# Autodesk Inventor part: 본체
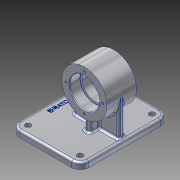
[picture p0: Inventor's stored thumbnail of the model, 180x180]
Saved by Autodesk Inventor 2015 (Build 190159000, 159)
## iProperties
Created: 2019-09
Part Number: 본체
Material: 알루미늄 6061
Document SubType Name: Modeling
Designer: Lineart
Density: 2.7 g/cm^3
Appearance: 알루미늄 - 평지
Mass: 554.62 g
Surface Area: 495.884 cm^2
Volume: 205.415 cm^3
Author: Lineart
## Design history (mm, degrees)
sketch "스케치1"
  geometry: L1 (-21, 0)-(21, 0); L2 (-21, 32)-(21, 32); L3 (-21, 21)-(-6, 21) reference; L4 (-21, 32)-(-21, 21) reference; L5 (21, 32)-(21, 21) reference; L6 (21, 21)-(6, 21) reference; L7 (6, 18)-(-6, 18) reference; L8 (-6, 18)-(-6, 21) reference; L9 (6, 21)-(6, 18); 2 further points
  constraints: 18 end point, 5 horizontal, 5 vertical, 1 coincident, 1 midpoint, 1 parallel, 1 perpendicular
  dimensions: "d0" = 42 distance of L1.start L1.end; "d1" = 32 distance between parallel lines of L1 L2; "d4" = 15 distance of L5.end L6.end
revolve "회전1" sketch "스케치1" stored, may be unused: angle "d6" = 90 deg
node "작업 평면1"
sketch "스케치2"
  geometry: L1 (0, 0)-(0, -62); L2 (63, -62)-(-63, -62); L3 (63, -62)-(63, 36); L4 (63, 36)-(-63, 36); L5 (-63, 36)-(-63, -62)
  constraints: 10 end point, 2 perpendicular, 2 vertical, 1 horizontal, 1 midpoint
  dimensions: "d8" = 62 distance of L1.end L1.start; "d9" = 126 distance of L2.start L2.end; "d10" = 98 distance of L2.start L3.end
extrude "돌출1" join sketch "스케치2" distance "d11" = 9; taper "d12" = 0 deg
sketch "스케치3"
  geometry: L1 (0, 32)-(-55.231, 32); L2 (-55.231, 32)-(-55.231, -32) reference; L3 (-55.231, -32)-(0, -32) reference; A1 r 32 centre (0, 0) between (0, 32) and (0, -32) reference; A2 r 32 centre (0, 0) between (0, 32) and (0, -32); 1 further point
  constraints: 6 end point, 4 point on circle, 2 horizontal, 2 perpendicular, 1 centre point, 1 coincident, 1 tangent, 1 vertical
extrude "돌출2" join sketch "스케치3" stored distance "d13" = 8; taper "d14" = 0 deg
sketch "스케치4"
  geometry: L1 (-17, -59)-(17, -59); L2 (-63, -59)-(63, -59) reference; L3 (-17, -22.009)-(17, -22.009) reference; L4 (-17, -22.009)-(-17, -59); L5 (17, -22.009)-(17, -59); 2 further points
  constraints: 8 end point, 2 horizontal, 2 midpoint, 2 vertical, 1 parallel
  dimensions: "d15" = 34 distance of L1.start L1.end
extrude "돌출3" join sketch "스케치4" stored distance "d16" = 8; taper "d17" = 0 deg
sketch "스케치5"
  geometry: L1 (0, 0)-(0, 26); 1 further point
  constraints: 2 end point, 1 coincident, 1 vertical
  dimensions: "d18" = 26 distance of L1.start L1.end
hole "구멍1" sketch "스케치5" at (0, 26) diameter "d19" = 3.242; stored, may be unused: countersink angle "d23" = 90 deg, drill point angle "d25" = 118 deg; dims "d20" = 8, "d21" = 4, "d22" = 2, "d24" = 10
fillet "모깎기1" dims "d29" = 12, "d30" = 3, "d46" = 0.3
fillet "모깎기2" dims "d31" = 3
chamfer "모따기1" distance "d32" = 1; stored, may be unused: second distance "d33" = 2, angle "d34" = 45 deg
sketch "스케치6"
  geometry: L1 (-51, -33)-(-5.472, -33) reference; L2 (1, -33.607)-(-1, -33.607) reference; L3 (7, -29)-(7, -7) reference; L4 (7, -7)-(14, -7) reference; L5 (20, -1)-(20, 1) reference; L6 (14, 7)-(7, 7) reference; L7 (7, 7)-(7, 29) reference; L8 (1, 35)-(-1, 35) reference; L9 (-7, 29)-(-7, 7) reference; L10 (-7, 7)-(-14, 7) reference; L11 (-20, 1)-(-20, -1) reference; L12 (-14, -7)-(-7, -7) reference; L13 (-7, -7)-(-7, -29) reference; L14 (-60, 50)-(-60, -24) reference; L15 (51, 59)-(-51, 59) reference; L16 (60, -24)-(60, 50) reference; L17 (5.472, -33)-(51, -33) reference; L18 (-63, 50)-(-63, 62); L19 (-63, 62)-(0, 62); L20 (51, 62)-(-51, 62) reference; L21 (0, 62)-(0, 52); A1 r 9 centre (-51, -24) between (-60, -24) and (-51, -33) reference; A2 r 6 centre (1, -29) between (5.472, -33) and (7, -29) reference; A3 r 6 centre (14, -1) between (14, -7) and (20, -1) reference; A4 r 6 centre (14, 1) between (20, 1) and (14, 7) reference; A5 r 6 centre (1, 29) between (7, 29) and (1, 35) reference; A6 r 6 centre (-1, 29) between (-1, 35) and (-7, 29) reference; A7 r 6 centre (-14, 1) between (-14, 7) and (-20, 1) reference; A8 r 6 centre (-14, -1) between (-20, -1) and (-14, -7) reference; A9 r 6 centre (-1, -29) between (-7, -29) and (-5.472, -33) reference; A10 r 9 centre (-51, 50) between (-51, 59) and (-60, 50) reference; A11 r 9 centre (51, 50) between (60, 50) and (51, 59) reference; A12 r 9 centre (51, -24) between (51, -33) and (60, -24) reference; A13 r 12 centre (-51, 50) between (-51, 62) and (-63, 50) reference; 2 further points
  constraints: 6 end point, 1 coincident, 1 midpoint, 1 perpendicular, 1 tangent, 1 vertical, 3 other
  dimensions: "d35" = 63 distance of L18.end L19.end; "d36" = 10 distance of L19.end L21.end
feature "엠보싱1" sketch "스케치6" dims "d37" = 0.5, "d38" = 0
sketch "스케치7"
  geometry: L1 (18.989, 51.997)-(17.659, 51.997) reference; L2 (17.659, 51.997)-(17.659, 52.377) reference; L3 (17.659, 52.377)-(18.989, 52.377) reference; L4 (18.989, 52.377)-(18.989, 54.955) reference; L5 (18.989, 54.955)-(19.315, 54.955) reference; L6 (19.45, 54.69)-(19.45, 49.018) reference; L7 (19.45, 49.018)-(18.989, 49.018) reference; L8 (18.989, 49.018)-(18.989, 51.997) reference; L9 (-13.942, 52.648)-(-13.942, 52.254) reference; L10 (-13.942, 52.254)-(-15.061, 52.254) reference; L11 (-15.061, 52.254)-(-15.061, 50.511) reference; L12 (-15.061, 50.511)-(-15.536, 50.511) reference; L13 (-15.536, 50.511)-(-15.536, 55.002) reference; L14 (-15.536, 55.002)-(-15.231, 55.002) reference; L15 (-15.061, 54.737)-(-15.061, 52.648) reference; L16 (-15.061, 52.648)-(-13.942, 52.648) reference; L17 (-14.844, 49.561)-(-14.844, 49.181) reference; L18 (-14.844, 49.181)-(-19.193, 49.181) reference; L19 (-19.193, 49.181)-(-19.193, 50.809) reference; L20 (-19.193, 50.809)-(-18.84, 50.809) reference; L21 (-18.731, 50.592)-(-18.731, 49.561) reference; L22 (-18.731, 49.561)-(-14.844, 49.561) reference; L23 (-17.374, 54.425)-(-18.853, 54.425) reference; L24 (-18.853, 54.425)-(-18.853, 54.778) reference; L25 (-18.853, 54.778)-(-17.374, 54.778) reference; L26 (-17.374, 54.778)-(-17.374, 54.425) reference; L27 (-20.047, 53.618)-(-20.047, 53.971) reference; L28 (-20.047, 53.971)-(-16.282, 53.971) reference; L29 (-16.282, 53.971)-(-16.282, 53.618) reference; L30 (-16.282, 53.618)-(-20.047, 53.618) reference; L31 (-2.917, 49.385)-(-3.474, 50.911) reference; L32 (-3.474, 50.911)-(-5.726, 50.911) reference; L33 (-5.726, 50.911)-(-6.296, 49.385) reference; L34 (-6.296, 49.385)-(-6.777, 49.385) reference; L35 (-6.777, 49.385)-(-4.878, 54.385) reference; L36 (-4.878, 54.385)-(-4.335, 54.385) reference; L37 (-4.335, 54.385)-(-2.436, 49.385) reference; L38 (-2.436, 49.385)-(-2.917, 49.385) reference; L39 (-4.613, 53.896)-(-5.57, 51.325) reference; L40 (-5.57, 51.325)-(-3.636, 51.325) reference; L41 (-3.636, 51.325)-(-4.613, 53.896) reference; L42 (-10.095, 51.149)-(-8.284, 51.149) reference; L43 (-8.284, 51.149)-(-8.284, 49.025) reference; L44 (-8.284, 49.025)-(-8.745, 49.025) reference; L45 (-8.745, 49.025)-(-8.745, 50.775) reference; L46 (-8.745, 50.775)-(-12.578, 50.775) reference; L47 (-12.578, 50.775)-(-12.578, 51.149) reference; L48 (-12.578, 51.149)-(-10.55, 51.149) reference; L49 (-10.55, 51.149)-(-10.55, 52.37) reference; L50 (-10.55, 52.37)-(-13.311, 52.37) reference; L51 (-13.311, 52.37)-(-13.311, 52.743) reference; L52 (-13.311, 52.743)-(-8.942, 52.743) reference; L53 (-8.657, 54.412)-(-12.463, 54.412) reference; L54 (-12.463, 54.412)-(-12.463, 54.792) reference; L55 (-12.463, 54.792)-(-8.175, 54.792) reference; L56 (-8.446, 52.743)-(-7.307, 52.743) reference; L57 (-7.307, 52.743)-(-7.307, 52.37) reference; L58 (-7.307, 52.37)-(-10.095, 52.37) reference; L59 (-10.095, 52.37)-(-10.095, 51.149) reference; L60 (1.526, 54.385)-(1.526, 53.971) reference; L61 (1.526, 53.971)-(-0.034, 53.971) reference; L62 (-0.034, 53.971)-(-0.034, 49.385) reference; L63 (-0.034, 49.385)-(-0.488, 49.385) reference; L64 (-0.488, 49.385)-(-0.488, 53.971) reference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; A1 r 9 centre (-51, -24) between (-60, -24) and (-51, -33) reference; A2 r 6 centre (1, -29) between (5.472, -33) and (7, -29) reference; A3 r 6 centre (14, -1) between (14, -7) and (20, -1) reference; A4 r 6 centre (14, 1) between (20, 1) and (14, 7) reference; A5 r 6 centre (1, 29) between (7, 29) and (1, 35) reference; A6 r 6 centre (-1, 29) between (-1, 35) and (-7, 29) reference; A7 r 6 centre (-14, 1) between (-14, 7) and (-20, 1) reference; A8 r 6 centre (-14, -1) between (-20, -1) and (-14, -7) reference; A9 r 6 centre (-1, -29) between (-7, -29) and (-5.472, -33) reference; A10 r 9 centre (-51, 50) between (-51, 59) and (-60, 50) reference; A11 r 9 centre (51, 50) between (60, 50) and (51, 59) reference; A12 r 9 centre (51, -24) between (51, -33) and (60, -24) reference; 66 further points
  constraints: 4 coincident, 78 other
hole "구멍2" sketch "스케치7" at (-51, 50), (-51, -24), (51, -24), (51, 50) diameter "d39" = 4.5; stored, may be unused: countersink angle "d43" = 90 deg, drill point angle "d45" = 0 deg; dims "d40" = 8, "d41" = 8, "d42" = 4.4, "d44" = 50
node "솔리드1"
pattern_circular "원형 패턴1" dims angle "d27" = 360 deg
mirror "대칭1"
node "절단 모서리 투영1"
node "절단 모서리 투영2"
other parameters: "d7" = -59
